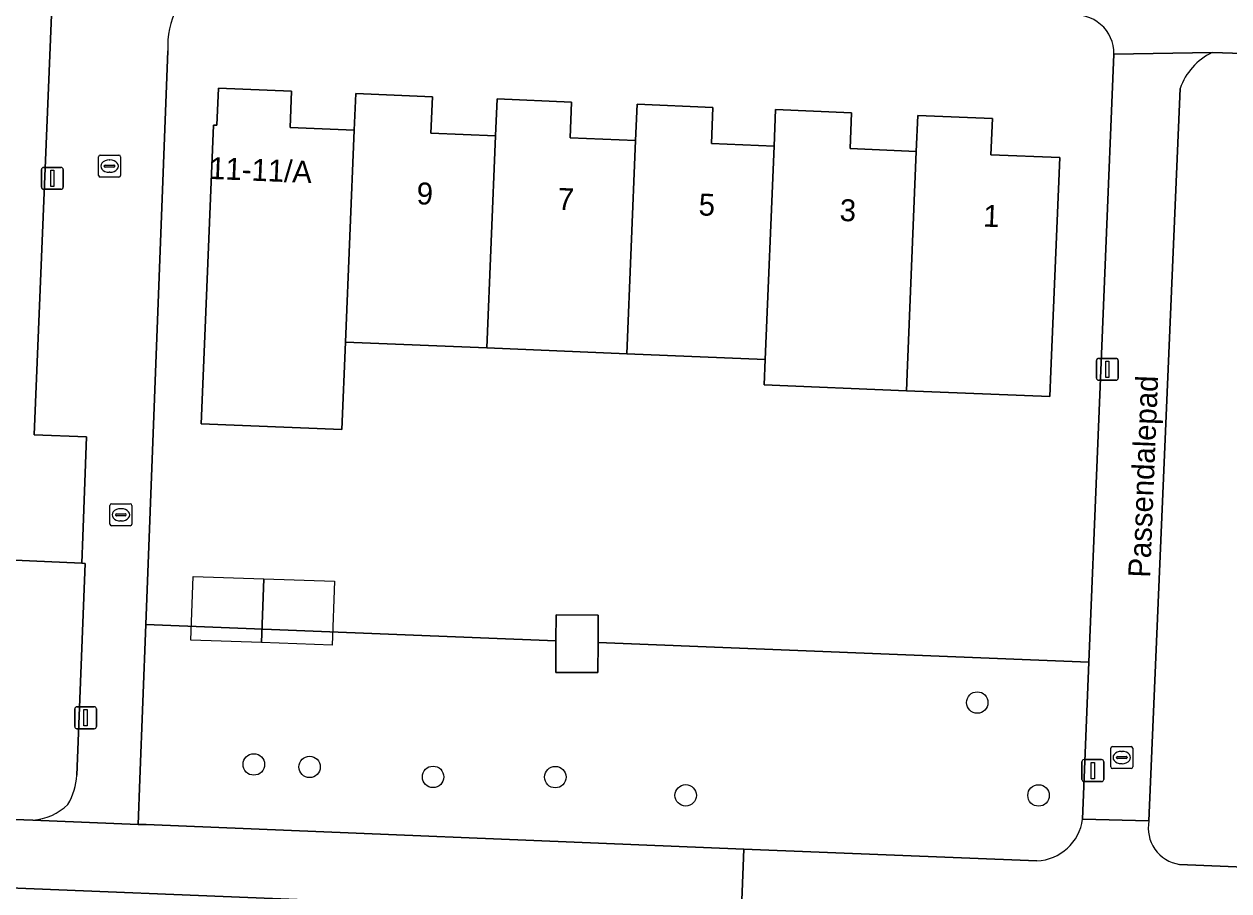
# Model space of a CAD drawing. Extents: x 160732 to 162107, y 387428 to 388479.
# Drawn here: x 161101.5 to 161156.4, y 387485.4 to 387524.9 of the extents above; entities that cross this region are included whole.
import ezdxf

# ---------------------------------------------------------------- set-up
doc = ezdxf.new("R2010")
doc.units = 0
for name, color, linetype in [('IMGEO_Boom', 7, 'Continuous'), ('IMGEO_Brandkraan', 7, 'Continuous'), ('IMGEO_Erf', 7, 'Continuous'), ('IMGEO_Fietspad_open', 7, 'Continuous'), ('IMGEO_Groenvoorziening', 7, 'Continuous'), ('IMGEO_Kolk', 7, 'Continuous'), ('IMGEO_Lichtmast', 7, 'Continuous'), ('IMGEO_Openbare_ruimte_label', 7, 'Continuous'), ('IMGEO_Pand', 7, 'Continuous'), ('IMGEO_Pand_nummerreeks', 7, 'Continuous'), ('IMGEO_Pand_vergunning_verleend', 7, 'Continuous'), ('IMGEO_Voetpad_open', 7, 'Continuous')]:
    doc.layers.add(name, color=color, linetype=linetype)

msp = doc.modelspace()

# ---------------------------------------------------------------- linework, layer by layer
at = {"layer": 'IMGEO_Boom'}
for centre in [(161144.906, 387494.003), (161111.928, 387491.176), (161114.47, 387491.066), (161120.1, 387490.611), (161125.67, 387490.598), (161131.615, 387489.768), (161147.699, 387489.763)]:
    msp.add_circle(centre, 0.489, dxfattribs=at)
at = {"layer": 'IMGEO_Brandkraan'}
for p, q in [((161150.994, 387491.067), (161150.994, 387491.919)), ((161151.069, 387491.993), (161151.921, 387491.993)), ((161151.482, 387491.773), (161151.507, 387491.773)), ((161151.995, 387491.919), (161151.995, 387491.067)), ((161151.253, 387491.487), (161151.253, 387491.499)), ((161151.691, 387491.45), (161151.293, 387491.45)), ((161151.296, 387491.536), (161151.694, 387491.536)), ((161151.505, 387491.213), (161151.48, 387491.213)), ((161151.737, 387491.499), (161151.737, 387491.487)), ((161151.921, 387490.993), (161151.069, 387490.993))]:
    msp.add_line(p, q, dxfattribs=at)
for points in [[(161150.994, 387491.067), (161150.994, 387491.919)], [(161151.069, 387491.993), (161151.921, 387491.993)], [(161151.995, 387491.919), (161151.995, 387491.067)], [(161151.921, 387490.993), (161151.069, 387490.993)]]:
    msp.add_lwpolyline(points, dxfattribs=at)
for centre, radius, start, end in [((161151.071, 387491.917), 0.0765, 91.552, 178.448), ((161151.071, 387491.917), 0.0765, 91.552, 178.448), ((161151.919, 387491.917), 0.0765, 1.552, 88.448), ((161151.919, 387491.917), 0.0765, 1.552, 88.448), ((161151.293, 387491.496), 0.0403, 85.8775, 175.7526), ((161151.29, 387491.486), 0.0366, 178.938, 274.7102), ((161151.694, 387491.493), 0.043, 264.8664, 352.4533), ((161151.698, 387491.498), 0.0386, 1.7309, 96.639), ((161151.071, 387491.069), 0.0765, 181.552, 268.448), ((161151.071, 387491.069), 0.0765, 181.552, 268.448), ((161151.919, 387491.069), 0.0765, 271.552, 358.448), ((161151.919, 387491.069), 0.0765, 271.552, 358.448)]:
    msp.add_arc(centre, radius, start, end, dxfattribs=at)
for centre, major_axis, ratio, start_param, end_param in [((161151.481, 387491.493), (-0.387, 0.002), 0.722429, 4.712389, 7.853982), ((161151.506, 387491.493), (-0.39, 0.002), 0.717154, 1.570796, 4.712389)]:
    msp.add_ellipse(centre, major_axis=major_axis, ratio=ratio, start_param=start_param, end_param=end_param, dxfattribs=at)
at = {"layer": 'IMGEO_Erf'}
for points in [[(161069.806, 387525.083), (161068.983, 387503.133), (161068.831, 387499.085), (161090.674, 387498.116), (161090.78, 387500.95), (161104.081, 387500.36), (161104.126, 387501.573), (161104.296, 387506.114), (161101.918, 387506.211), (161102.795, 387527.593)], [(161108.014, 387523.721), (161107.002, 387497.56), (161125.701, 387496.813), (161125.706, 387497.995), (161127.624, 387497.988), (161127.619, 387496.736), (161149.999, 387495.842), (161151.135, 387523.581)], [(161179.605, 387514.324), (161181.288, 387514.248), (161181.291, 387514.309), (161183.783, 387514.213), (161183.925, 387516.712), (161181.402, 387516.79), (161181.521, 387520.678), (161184.044, 387520.601), (161184.13, 387522.307), (161160.272, 387523.503), (161155.612, 387523.647)], [(161154.156, 387522.01), (161152.73, 387488.6)], [(161154.118, 387486.619), (161182.577, 387485.439), (161182.992, 387495.447), (161180.515, 387495.539), (161180.662, 387499.513), (161180.748, 387501.835), (161183.226, 387501.743), (161183.335, 387504.177), (161180.842, 387504.27), (161181.012, 387508.075), (161181.175, 387511.719), (161179.492, 387511.795), (161179.605, 387514.324)]]:
    msp.add_lwpolyline(points, dxfattribs=at)
msp.add_lwpolyline([(161148.267, 387509.118), (161148.219, 387507.954), (161141.676, 387508.223), (161135.197, 387508.49), (161135.245, 387509.654), (161128.93, 387509.914), (161122.551, 387510.177), (161116.107, 387510.442), (161115.943, 387506.449), (161109.532, 387506.713), (161109.696, 387510.706), (161110.092, 387520.336), (161110.242, 387520.33), (161110.311, 387522.024), (161113.648, 387521.886), (161113.581, 387520.237), (161116.506, 387520.117), (161116.574, 387521.781), (161120.071, 387521.637), (161120.003, 387519.978), (161122.95, 387519.857), (161123.019, 387521.534), (161126.415, 387521.394), (161126.348, 387519.767), (161129.332, 387519.645), (161129.4, 387521.291), (161132.854, 387521.149), (161132.786, 387519.5), (161135.647, 387519.382), (161135.715, 387521.045), (161139.177, 387520.903), (161139.109, 387519.266), (161142.125, 387519.142), (161142.193, 387520.784), (161145.595, 387520.644), (161145.527, 387518.986), (161148.668, 387518.857)], close=True, dxfattribs=at)
for centre, radius, start, end in [((161111.376, 387524.019), 3.376, 116.733, 185.0668), ((161149.391, 387523.617), 1.744, 358.8285, 99.5339), ((161156.84, 387521.088), 2.838, 115.6465, 161.0517), ((161154.378, 387488.278), 1.679, 168.9385, 261.096)]:
    msp.add_arc(centre, radius, start, end, dxfattribs=at)
at = {"layer": 'IMGEO_Fietspad_open'}
msp.add_lwpolyline([(161134.151, 387484.191), (161079.41, 387486.41), (161032.946, 387488.45), (161000, 387489.783), (160964.882, 387491.216), (160955.896, 387491.483), (160945.905, 387492.112), (160935.793, 387493.329), (160911.562, 387497.191), (160901.233, 387498.754), (160891.554, 387500.319), (160862.38, 387504.81), (160820.517, 387511.401), (160801.558, 387514.26)], dxfattribs=at)
at = {"layer": 'IMGEO_Groenvoorziening'}
for points in [[(161062.574, 387581.461), (161065.553, 387581.331), (161066.088, 387597.32), (161052.673, 387598.338), (161051.995, 387580.571), (161057.641, 387580.351), (161056.619, 387549.786), (161060.139, 387540.51), (161058.424, 387500), (161052.967, 387500.177), (161052.958, 387500), (161052.49, 387490.824), (161052.92, 387490.805), (161068.496, 387490.143), (161086.862, 387489.194), (161101.855, 387488.631)], [(161103.862, 387490.688), (161104.237, 387500.35), (161104.081, 387500.36), (161090.78, 387500.95), (161090.674, 387498.116), (161068.831, 387499.085), (161068.983, 387503.133), (161069.806, 387525.083), (161067.968, 387525.152), (161068.211, 387531.677), (161070.05, 387531.608), (161070.371, 387540.152), (161068.685, 387540.215), (161068.841, 387544.404), (161070.528, 387544.341), (161071.084, 387559.187), (161068.672, 387559.323), (161064.436, 387559.509), (161061.624, 387559.645), (161062.574, 387581.461)], [(161149.999, 387495.842), (161127.619, 387496.736), (161127.614, 387495.372), (161125.696, 387495.379), (161125.701, 387496.813), (161107.002, 387497.56), (161106.73, 387490.51), (161106.65, 387488.446), (161107.019, 387488.431), (161134.267, 387487.321), (161147.626, 387486.777)], [(161149.706, 387488.686), (161149.999, 387495.842)]]:
    msp.add_lwpolyline(points, dxfattribs=at)
for centre, radius, start, end in [((161100.724, 387490.912), 3.146, 330.2744, 355.9184), ((161101.629, 387491.27), 2.649, 274.8888, 313.5994), ((161147.528, 387488.972), 2.197, 272.5667, 352.524)]:
    msp.add_arc(centre, radius, start, end, dxfattribs=at)
at = {"layer": 'IMGEO_Kolk'}
for p, q in [((161104.85, 387518.044), (161104.85, 387518.896)), ((161104.925, 387518.97), (161105.777, 387518.97)), ((161105.338, 387518.75), (161105.363, 387518.75)), ((161105.851, 387518.896), (161105.851, 387518.044)), ((161105.109, 387518.464), (161105.109, 387518.476)), ((161105.547, 387518.427), (161105.149, 387518.427)), ((161105.152, 387518.513), (161105.55, 387518.513)), ((161105.361, 387518.19), (161105.336, 387518.19)), ((161105.593, 387518.476), (161105.593, 387518.464)), ((161105.777, 387517.97), (161104.925, 387517.97)), ((161105.367, 387502.139), (161105.367, 387502.991)), ((161105.442, 387503.065), (161106.294, 387503.065)), ((161105.855, 387502.845), (161105.88, 387502.845)), ((161106.368, 387502.991), (161106.368, 387502.139)), ((161105.626, 387502.559), (161105.626, 387502.571)), ((161106.064, 387502.522), (161105.666, 387502.522)), ((161105.669, 387502.608), (161106.067, 387502.608)), ((161105.878, 387502.285), (161105.853, 387502.285)), ((161106.11, 387502.571), (161106.11, 387502.559)), ((161106.294, 387502.065), (161105.442, 387502.065))]:
    msp.add_line(p, q, dxfattribs=at)
for points in [[(161104.85, 387518.044), (161104.85, 387518.896)], [(161104.925, 387518.97), (161105.777, 387518.97)], [(161105.851, 387518.896), (161105.851, 387518.044)], [(161105.777, 387517.97), (161104.925, 387517.97)], [(161105.367, 387502.139), (161105.367, 387502.991)], [(161105.442, 387503.065), (161106.294, 387503.065)], [(161106.368, 387502.991), (161106.368, 387502.139)], [(161106.294, 387502.065), (161105.442, 387502.065)]]:
    msp.add_lwpolyline(points, dxfattribs=at)
for centre, radius, start, end in [((161104.927, 387518.894), 0.0765, 91.552, 178.448), ((161104.927, 387518.894), 0.0765, 91.552, 178.448), ((161105.775, 387518.894), 0.0765, 1.552, 88.448), ((161105.775, 387518.894), 0.0765, 1.552, 88.448), ((161105.149, 387518.473), 0.0403, 85.8775, 175.7526), ((161105.146, 387518.463), 0.0366, 178.938, 274.7102), ((161105.55, 387518.47), 0.043, 264.8664, 352.4533), ((161105.554, 387518.475), 0.0386, 1.7309, 96.639), ((161104.927, 387518.046), 0.0765, 181.552, 268.448), ((161104.927, 387518.046), 0.0765, 181.552, 268.448), ((161105.775, 387518.046), 0.0765, 271.552, 358.448), ((161105.775, 387518.046), 0.0765, 271.552, 358.448), ((161105.444, 387502.989), 0.0765, 91.552, 178.448), ((161105.444, 387502.989), 0.0765, 91.552, 178.448), ((161106.292, 387502.989), 0.0765, 1.552, 88.448), ((161106.292, 387502.989), 0.0765, 1.552, 88.448), ((161105.666, 387502.568), 0.0403, 85.8775, 175.7526), ((161105.663, 387502.558), 0.0366, 178.938, 274.7102), ((161106.067, 387502.565), 0.043, 264.8664, 352.4533), ((161106.071, 387502.57), 0.0386, 1.7309, 96.639), ((161105.444, 387502.141), 0.0765, 181.552, 268.448), ((161105.444, 387502.141), 0.0765, 181.552, 268.448), ((161106.292, 387502.141), 0.0765, 271.552, 358.448), ((161106.292, 387502.141), 0.0765, 271.552, 358.448)]:
    msp.add_arc(centre, radius, start, end, dxfattribs=at)
for centre, major_axis, ratio, start_param, end_param in [((161105.337, 387518.47), (-0.387, 0.002), 0.722429, 4.712389, 7.853982), ((161105.362, 387518.47), (-0.39, 0.002), 0.717154, 1.570796, 4.712389), ((161105.854, 387502.565), (-0.387, 0.002), 0.722429, 4.712389, 7.853982), ((161105.879, 387502.565), (-0.39, 0.002), 0.717154, 1.570796, 4.712389)]:
    msp.add_ellipse(centre, major_axis=major_axis, ratio=ratio, start_param=start_param, end_param=end_param, dxfattribs=at)
at = {"layer": 'IMGEO_Lichtmast'}
for p, q in [((161102.247, 387517.511), (161102.247, 387518.311)), ((161102.247, 387518.311), (161102.247, 387517.511)), ((161102.347, 387518.411), (161103.137, 387518.411)), ((161103.137, 387518.411), (161102.347, 387518.411)), ((161103.237, 387518.311), (161103.237, 387517.511)), ((161103.237, 387517.511), (161103.237, 387518.311)), ((161103.137, 387517.411), (161102.347, 387517.411)), ((161102.347, 387517.411), (161103.137, 387517.411)), ((161150.341, 387508.801), (161150.341, 387509.601)), ((161150.341, 387509.601), (161150.341, 387508.801)), ((161150.441, 387509.701), (161151.231, 387509.701)), ((161151.231, 387509.701), (161150.441, 387509.701)), ((161151.331, 387509.601), (161151.331, 387508.801)), ((161151.331, 387508.801), (161151.331, 387509.601)), ((161151.231, 387508.701), (161150.441, 387508.701)), ((161150.441, 387508.701), (161151.231, 387508.701)), ((161103.764, 387492.907), (161103.764, 387493.707)), ((161103.764, 387493.707), (161103.764, 387492.907)), ((161103.864, 387493.807), (161104.654, 387493.807)), ((161104.654, 387493.807), (161103.864, 387493.807)), ((161104.754, 387493.707), (161104.754, 387492.907)), ((161104.754, 387492.907), (161104.754, 387493.707)), ((161104.654, 387492.807), (161103.864, 387492.807)), ((161103.864, 387492.807), (161104.654, 387492.807)), ((161149.68, 387490.498), (161149.68, 387491.298)), ((161149.68, 387491.298), (161149.68, 387490.498)), ((161149.78, 387491.398), (161150.57, 387491.398)), ((161150.57, 387491.398), (161149.78, 387491.398)), ((161150.67, 387491.298), (161150.67, 387490.498)), ((161150.67, 387490.498), (161150.67, 387491.298)), ((161150.57, 387490.398), (161149.78, 387490.398)), ((161149.78, 387490.398), (161150.57, 387490.398))]:
    msp.add_line(p, q, dxfattribs=at)
for points in [[(161102.667, 387518.286), (161102.817, 387518.286), (161102.817, 387517.536), (161102.667, 387517.536), (161102.667, 387518.286)], [(161150.761, 387509.576), (161150.911, 387509.576), (161150.911, 387508.826), (161150.761, 387508.826), (161150.761, 387509.576)], [(161104.184, 387493.682), (161104.334, 387493.682), (161104.334, 387492.932), (161104.184, 387492.932), (161104.184, 387493.682)], [(161150.1, 387491.273), (161150.25, 387491.273), (161150.25, 387490.523), (161150.1, 387490.523), (161150.1, 387491.273)]]:
    msp.add_lwpolyline(points, dxfattribs=at)
for centre, start, end in [((161102.347, 387518.311), 90, 180), ((161102.347, 387518.311), 90, 180), ((161103.137, 387518.311), 0, 90), ((161103.137, 387518.311), 360, 90), ((161102.347, 387517.511), 180, 270), ((161102.347, 387517.511), 180, 270), ((161103.137, 387517.511), 270, 0), ((161103.137, 387517.511), 270, 0), ((161150.441, 387509.601), 90, 180), ((161150.441, 387509.601), 90, 180), ((161151.231, 387509.601), 0, 90), ((161151.231, 387509.601), 360, 90), ((161150.441, 387508.801), 180, 270), ((161150.441, 387508.801), 180, 270), ((161151.231, 387508.801), 270, 0), ((161151.231, 387508.801), 270, 0), ((161103.864, 387493.707), 90, 180), ((161103.864, 387493.707), 90, 180), ((161104.654, 387493.707), 0, 90), ((161104.654, 387493.707), 360, 90), ((161103.864, 387492.907), 180, 270), ((161103.864, 387492.907), 180, 270), ((161104.654, 387492.907), 270, 0), ((161104.654, 387492.907), 270, 0), ((161149.78, 387491.298), 90, 180), ((161149.78, 387491.298), 90, 180), ((161150.57, 387491.298), 0, 90), ((161150.57, 387491.298), 360, 90), ((161149.78, 387490.498), 180, 270), ((161149.78, 387490.498), 180, 270), ((161150.57, 387490.498), 270, 0), ((161150.57, 387490.498), 270, 0)]:
    msp.add_arc(centre, 0.1, start, end, dxfattribs=at)
at = {"layer": 'IMGEO_Pand'}
for points in [[(161116.506, 387520.117), (161113.581, 387520.237), (161113.648, 387521.886), (161110.311, 387522.024), (161110.242, 387520.33), (161110.092, 387520.336), (161109.696, 387510.706), (161109.532, 387506.713), (161115.943, 387506.449), (161116.107, 387510.442)], [(161116.107, 387510.442), (161122.551, 387510.177), (161122.95, 387519.857), (161120.003, 387519.978), (161120.071, 387521.637), (161116.574, 387521.781), (161116.506, 387520.117)], [(161122.551, 387510.177), (161128.93, 387509.914), (161129.332, 387519.645), (161126.348, 387519.767), (161126.415, 387521.394), (161123.019, 387521.534), (161122.95, 387519.857)], [(161135.647, 387519.382), (161132.786, 387519.5), (161132.854, 387521.149), (161129.4, 387521.291), (161129.332, 387519.645), (161128.93, 387509.914), (161135.245, 387509.654)], [(161142.125, 387519.142), (161139.109, 387519.266), (161139.177, 387520.903), (161135.715, 387521.045), (161135.647, 387519.382), (161135.245, 387509.654), (161135.197, 387508.49), (161141.676, 387508.223), (161141.724, 387509.387)], [(161148.668, 387518.857), (161145.527, 387518.986), (161145.595, 387520.644), (161142.193, 387520.784), (161142.125, 387519.142), (161141.724, 387509.387), (161141.676, 387508.223), (161148.219, 387507.954), (161148.267, 387509.118)], [(161125.701, 387496.813), (161125.696, 387495.379), (161127.614, 387495.372), (161127.619, 387496.736), (161127.624, 387497.988), (161125.706, 387497.995)]]:
    msp.add_lwpolyline(points, close=True, dxfattribs=at)
at = {"layer": 'IMGEO_Pand_vergunning_verleend'}
for points in [[(161109.059, 387496.847), (161109.16, 387499.758), (161112.379, 387499.647), (161112.279, 387496.736)], [(161112.279, 387496.736), (161112.379, 387499.647), (161115.598, 387499.536), (161115.498, 387496.625)]]:
    msp.add_lwpolyline(points, close=True, dxfattribs=at)
at = {"layer": 'IMGEO_Voetpad_open'}
for points in [[(161109.858, 387527.034), (161102.795, 387527.593), (161101.918, 387506.211), (161104.296, 387506.114), (161104.126, 387501.573), (161104.081, 387500.36), (161104.237, 387500.35), (161103.862, 387490.688)], [(161101.855, 387488.631), (161106.65, 387488.446), (161106.73, 387490.51), (161107.002, 387497.56), (161108.014, 387523.721)], [(161155.612, 387523.647), (161151.135, 387523.581), (161149.999, 387495.842), (161149.706, 387488.686), (161152.73, 387488.6), (161154.156, 387522.01)], [(161151.135, 387523.581), (161155.612, 387523.647), (161160.272, 387523.503), (161184.13, 387522.307), (161185.704, 387522.228), (161185.708, 387522.327), (161189.398, 387522.163), (161193.088, 387521.999), (161195.84, 387521.892), (161199.512, 387521.714), (161203.184, 387521.537), (161205.804, 387521.398), (161209.478, 387521.273), (161213.15, 387521.148), (161215.898, 387521.014), (161219.534, 387520.868), (161223.17, 387520.722), (161224.71, 387520.643), (161228.212, 387520.523), (161236.726, 387520.113), (161243.712, 387519.822), (161247.623, 387519.76), (161247.682, 387522.742), (161244.661, 387522.856)], [(161134.267, 387487.321), (161107.019, 387488.431), (161106.65, 387488.446), (161101.855, 387488.631), (161086.862, 387489.194), (161068.496, 387490.143), (161052.92, 387490.805), (161052.49, 387490.824), (161049.856, 387490.938), (161049.493, 387490.954), (161033.032, 387491.6), (161004.213, 387492.732), (161000, 387492.895), (160981.676, 387493.606), (160979.317, 387493.697), (160979.097, 387493.706), (160959.839, 387494.526), (160946.036, 387495.354), (160936.105, 387496.525), (160913.899, 387500), (160803.773, 387517.234), (160800.633, 387517.855)], [(160801.558, 387514.26), (160820.517, 387511.401), (160862.38, 387504.81), (160891.554, 387500.319), (160901.233, 387498.754), (160911.562, 387497.191), (160935.793, 387493.329), (160945.905, 387492.112), (160955.896, 387491.483), (160964.882, 387491.216), (161000, 387489.783), (161032.946, 387488.45), (161079.41, 387486.41), (161134.151, 387484.191), (161134.267, 387487.321)], [(161152.73, 387488.6), (161149.706, 387488.686)], [(161147.626, 387486.777), (161134.267, 387487.321), (161134.151, 387484.191), (161246.605, 387479.634), (161252.434, 387479.398)], [(161244.186, 387482.887), (161223.215, 387483.756), (161221.687, 387483.819), (161184.131, 387485.375), (161182.577, 387485.439), (161154.118, 387486.619)]]:
    msp.add_lwpolyline(points, dxfattribs=at)
for centre, radius, start, end in [((161111.376, 387524.019), 3.376, 116.733, 185.0668), ((161149.391, 387523.617), 1.744, 358.8285, 99.5339), ((161156.84, 387521.088), 2.838, 115.6465, 161.0517), ((161100.724, 387490.912), 3.146, 330.2744, 355.9184), ((161101.629, 387491.27), 2.649, 274.8888, 313.5994), ((161147.528, 387488.972), 2.197, 272.5667, 352.524), ((161154.378, 387488.278), 1.679, 168.9385, 261.096)]:
    msp.add_arc(centre, radius, start, end, dxfattribs=at)

# ---------------------------------------------------------------- texts
at = {"layer": 'IMGEO_Openbare_ruimte_label'}
msp.add_text('Passendalepad', height=1, rotation=87.7071, dxfattribs=at).set_placement((161152.783, 387499.685))
at = {"layer": 'IMGEO_Pand_nummerreeks'}
for s, rotation, p in [('11-11/A', 357.6509, (161109.877, 387517.887)), ('9', 357.7389, (161119.333, 387516.733)), ('7', 357.7389, (161125.762, 387516.479)), ('5', 357.7389, (161132.191, 387516.225)), ('3', 357.7368, (161138.619, 387515.971)), ('1', 357.7368, (161145.162, 387515.713))]:
    msp.add_text(s, height=1, rotation=rotation, dxfattribs=at).set_placement(p)

doc.saveas('drawing.dxf')
